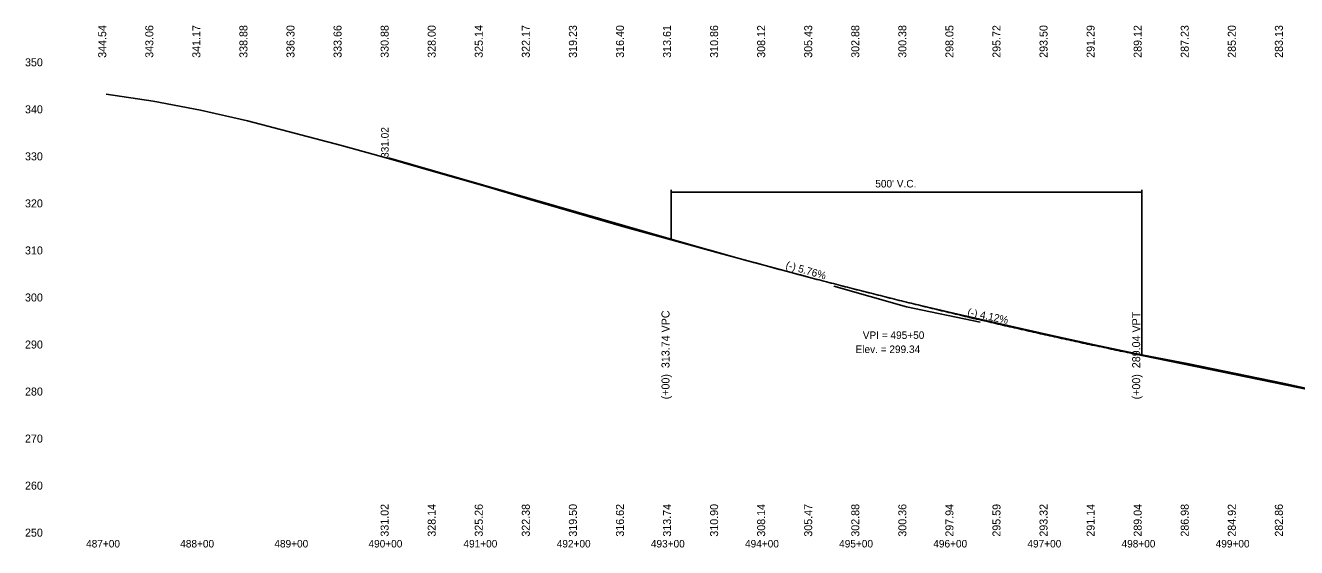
# Model space of a CAD drawing. Extents: x 49241 to 62599, y 49216 to 56011.
# Drawn here: x 57098 to 58449, y 53749 to 54304 of the extents above; entities that cross this region are included whole.
import ezdxf

# ---------------------------------------------------------------- set-up
doc = ezdxf.new("R2010")
doc.units = 0
for name, color, linetype in [('Level 40', 7, 'Continuous'), ('Level 41', 7, 'Continuous'), ('Level 42', 7, 'Continuous'), ('Level 43', 7, 'Continuous'), ('Level 45', 7, 'Continuous')]:
    doc.layers.add(name, color=color, linetype=linetype)

msp = doc.modelspace()

# ---------------------------------------------------------------- linework, layer by layer
at = {"layer": 'Level 40'}
msp.add_lwpolyline([(57184.2, 54230.5), (57234.2, 54223.1), (57284.2, 54213.6), (57334.2, 54202.2), (57384.2, 54189.3), (57434.2, 54176.1), (57484.2, 54162.2), (57534.2, 54147.8), (57584.2, 54133.5), (57634.2, 54118.6), (57684.2, 54104), (57734.2, 54089.8), (57784.2, 54075.9), (57834.2, 54062.1), (57884.2, 54048.4), (57934.2, 54034.9), (57984.2, 54022.2), (58034.2, 54009.7), (58084.2, 53998), (58134.2, 53986.4), (58184.2, 53975.3), (58234.2, 53964.3), (58284.2, 53953.4), (58334.2, 53943.9), (58384.2, 53933.8), (58434.2, 53923.4), (58484.2, 53912.5)], dxfattribs=at)
at = {"layer": 'Level 41'}
for p, q in [((57784.2, 54129), (57784.2, 54076.5)), ((57784.2, 54126.5), (58284.2, 54126.5)), ((58284.2, 54129), (58284.2, 53953)), ((57957.3, 54026.6), (58034.2, 54004.5)), ((58112.5, 53988.3), (58034.2, 54004.5))]:
    msp.add_line(p, q, dxfattribs=at)
at = {"layer": 'Level 45'}
for p, q in [((57484.2, 54162.9), (57784.2, 54076.5)), ((58284.2, 53953), (58484.2, 53911.8))]:
    msp.add_line(p, q, dxfattribs=at)
msp.add_spline([(57784.2, 54076.5), (57794.2, 54073.6), (57804.2, 54070.8), (57814.2, 54067.9), (57824.2, 54065.1), (57834.2, 54062.3), (57844.2, 54059.5), (57854.2, 54056.7), (57864.2, 54054), (57874.2, 54051.2), (57884.2, 54048.5), (57894.2, 54045.8), (57904.2, 54043.1), (57914.2, 54040.4), (57924.2, 54037.8), (57934.2, 54035.1), (57944.2, 54032.5), (57954.2, 54029.9), (57964.2, 54027.3), (57974.2, 54024.7), (57984.2, 54022.2), (57994.2, 54019.6), (58004.2, 54017.1), (58014.2, 54014.6), (58024.2, 54012.1), (58034.2, 54009.6), (58044.2, 54007.2), (58054.2, 54004.7), (58064.2, 54002.3), (58074.2, 53999.9), (58084.2, 53997.5), (58094.2, 53995.1), (58104.2, 53992.7), (58114.2, 53990.4), (58124.2, 53988), (58134.2, 53985.7), (58144.2, 53983.4), (58154.2, 53981.2), (58164.2, 53978.9), (58174.2, 53976.6), (58184.2, 53974.4), (58194.2, 53972.2), (58204.2, 53970), (58214.2, 53967.8), (58224.2, 53965.6), (58234.2, 53963.5), (58244.2, 53961.4), (58254.2, 53959.2), (58264.2, 53957.1), (58274.2, 53955.1), (58284.2, 53953)], degree=3, dxfattribs=at)

# ---------------------------------------------------------------- texts
at = {"layer": 'Level 41'}
for s, height, rotation, p in [('331.02', 8, 90, (57484.2, 54162.9)), ('(-) 5.76%', 8, 343.9336, (57905.4, 54045.7)), ('(-) 4.12%', 8, 348.3599, (58098.5, 53995.3)), ('(+00)  313.74 VPC', 8.5, 90, (57782.6, 53906.3)), ('(+00)  289.04 VPT', 8.5, 90, (58282.6, 53906.2))]:
    msp.add_text(s, height=height, rotation=rotation, dxfattribs=at).set_placement(p)
for s, p in [("500' V.C.", (58001.2, 54131.5)), ('VPI = 495+50', (57987.9, 53970.5)), ('Elev. = 299.34', (57980.2, 53955.5))]:
    msp.add_text(s, height=8, dxfattribs=at).set_placement(p)
at = {"layer": 'Level 42'}
for s, height, p in [('350', 8.5, (57097.9, 54260.3)), ('340', 8.5, (57097.9, 54210.3)), ('330', 8.5, (57097.9, 54160.3)), ('320', 8.5, (57097.9, 54110.3)), ('310', 8.5, (57097.9, 54060.3)), ('300', 8.5, (57097.9, 54010.3)), ('290', 8.5, (57097.9, 53960.3)), ('280', 8.5, (57097.9, 53910.3)), ('270', 8.5, (57097.9, 53860.3)), ('260', 8.5, (57097.9, 53810.3)), ('250', 8.5, (57097.9, 53760.3)), ('487+00', 8, (57162.8, 53748.8)), ('488+00', 8, (57262.8, 53748.8)), ('489+00', 8, (57362.8, 53748.8)), ('490+00', 8, (57462.8, 53748.8)), ('491+00', 8, (57563.7, 53748.8)), ('492+00', 8, (57662.8, 53748.8)), ('493+00', 8, (57762.8, 53748.8)), ('494+00', 8, (57862.8, 53748.8)), ('495+00', 8, (57962.8, 53748.8)), ('496+00', 8, (58062.8, 53748.8)), ('497+00', 8, (58162.8, 53748.8)), ('498+00', 8, (58262.8, 53748.8)), ('499+00', 8, (58362.8, 53748.8))]:
    msp.add_text(s, height=height, dxfattribs=at).set_placement(p)
at = {"layer": 'Level 43'}
for s, p in [('344.54', (57184.2, 54269.3)), ('343.06', (57234.2, 54269.3)), ('341.17', (57284.2, 54269.3)), ('338.88', (57334.2, 54269.3)), ('336.30', (57384.2, 54269.3)), ('333.66', (57434.2, 54269.3)), ('330.88', (57484.2, 54269.3)), ('328.00', (57534.2, 54269.3)), ('325.14', (57584.2, 54269.3)), ('322.17', (57634.2, 54269.3)), ('319.23', (57684.2, 54269.3)), ('316.40', (57734.2, 54269.3)), ('313.61', (57784.2, 54269.3)), ('310.86', (57834.2, 54269.3)), ('308.12', (57884.2, 54269.3)), ('305.43', (57934.2, 54269.3)), ('302.88', (57984.2, 54269.3)), ('300.38', (58034.2, 54269.3)), ('298.05', (58084.2, 54269.3)), ('295.72', (58134.2, 54269.3)), ('293.50', (58184.2, 54269.3)), ('291.29', (58234.2, 54269.3)), ('289.12', (58284.2, 54269.3)), ('287.23', (58334.2, 54269.3)), ('285.20', (58384.2, 54269.3)), ('283.13', (58434.2, 54269.3)), ('331.02', (57484.2, 53760.3)), ('328.14', (57534.2, 53760.3)), ('325.26', (57584.2, 53760.3)), ('322.38', (57634.2, 53760.3)), ('319.50', (57684.2, 53760.3)), ('316.62', (57734.2, 53760.3)), ('313.74', (57784.2, 53760.3)), ('310.90', (57834.2, 53760.3)), ('308.14', (57884.2, 53760.3)), ('305.47', (57934.2, 53760.3)), ('302.88', (57984.2, 53760.3)), ('300.36', (58034.2, 53760.3)), ('297.94', (58084.2, 53760.3)), ('295.59', (58134.2, 53760.3)), ('293.32', (58184.2, 53760.3)), ('291.14', (58234.2, 53760.3)), ('289.04', (58284.2, 53760.3)), ('286.98', (58334.2, 53760.3)), ('284.92', (58384.2, 53760.3)), ('282.86', (58434.2, 53760.3))]:
    msp.add_text(s, height=8.5, rotation=90, dxfattribs=at).set_placement(p)

doc.saveas('drawing.dxf')
